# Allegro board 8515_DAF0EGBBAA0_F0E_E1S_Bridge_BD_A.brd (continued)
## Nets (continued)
IRQ_P12V_E1S_0_FLT_N: R171.1 U3.6 U22.C7 U35.N4
IRQ_P12V_E1S_1_FLT_N: R174.1 U4.6 U23.C7 U35.P4
IRQ_P12V_E1S_2_FLT_N: R179.1 U5.6 U24.C7 U35.P1
IRQ_P12V_E1S_3_FLT_N: R182.1 U6.6 U25.C7 U35.P5
IRQ_P12V_EDGE_FLT_N: R4589.2 U35.T11
IRQ_P12V_EDGE_FLT_N_R: R512.2 R4589.1 U33.C7 U34.9
IRQ_P12V_HSC_ALERT1_N: R707.2 U35.R3
IRQ_P12V_HSC_ALERT2_N: R708.2 U35.T2
IRQ_SMB_ALERT_N: GF1.OCP_A11 R185.2 R552.1
IRQ_SMB_ALERT_R_N: R552.2 U35.P9
IRQ_TMP75_ALERT_N: R291.1 U35.L4
JTAG_BIC_DEBUG_R_TDO: R674.2 U35.A11
JTAG_BIC_DEBUG_TCK: R4585.2 U35.D10
JTAG_BIC_DEBUG_TCK2: R4615.2 U35.A13
JTAG_BIC_DEBUG_TCK_R: J2.4 R4581.1 R4585.1
JTAG_BIC_DEBUG_TDI: R4586.2 U35.C10
JTAG_BIC_DEBUG_TDI2: R4616.2 U35.D11
JTAG_BIC_DEBUG_TDI_R: J2.8 R4582.1 R4586.1
JTAG_BIC_DEBUG_TDO: J2.6 R674.1 R4583.1
JTAG_BIC_DEBUG_TDO2: R4617.2 U35.C11
JTAG_BIC_DEBUG_TMS: R4584.2 U35.B11
JTAG_BIC_DEBUG_TMS2: R4618.2 U35.B12
JTAG_BIC_DEBUG_TMS_R: J2.2 R4580.1 R4584.1
JTAG_BIC_NTRST1: R596.2 R675.2 U35.A12
JTAG_BIC_NTRST2: R4613.2 R4614.2 U35.B13
JTAG_BIC_SRST_N: J2.10 R4587.1
LED_BIC_E1S_0: J4.A10 R216.1 R551.2
LED_BIC_E1S_1: J5.A10 R231.1 R553.2
LED_BIC_E1S_2: J6.A10 R246.1 R554.2
LED_BIC_E1S_3: J7.A10 R261.1 R725.2
LED_BIC_E1S_R_0: R551.1 U35.R11
LED_BIC_E1S_R_1: R553.1 U35.T12
LED_BIC_E1S_R_2: R554.1 U35.R12
LED_BIC_E1S_R_3: R725.1 U35.T13
LED_P12V_AUX: D10.1 R296.2
LED_P12V_E1S_ALL_GOOD: D11.C(\C\) U17.D
LED_P12V_E1S_ALL_GOOD_R: D11.A R297.2
LED_PWRGD_P12V_E1S_ALL: R298.1 R4670.1 U35.N5
LED_PWRGD_P12V_E1S_ALL_R: C304.1 R4670.2 U17.G
OSC1_OE: OSC1.1 R319.1
OSC1_VDD: C236.1 L6.2 OSC1.4(\VDD\) R661.1
OSC1_VDD_R: C237.1 R661.2
P3E_E1S_0_RX_DN0: GF1.A17 J4.A17
P3E_E1S_0_RX_DN1: GF1.A20 J4.A20
P3E_E1S_0_RX_DN2: GF1.A23 J4.A23
P3E_E1S_0_RX_DN3: GF1.A26 J4.A26
P3E_E1S_0_RX_DP0: GF1.A18 J4.A18
P3E_E1S_0_RX_DP1: GF1.A21 J4.A21
P3E_E1S_0_RX_DP2: GF1.A24 J4.A24
P3E_E1S_0_RX_DP3: GF1.A27 J4.A27
P3E_E1S_0_TX_DN0: GF1.B17 J4.B17
P3E_E1S_0_TX_DN1: GF1.B20 J4.B20
P3E_E1S_0_TX_DN2: GF1.B23 J4.B23
P3E_E1S_0_TX_DN3: GF1.B26 J4.B26
P3E_E1S_0_TX_DP0: GF1.B18 J4.B18
P3E_E1S_0_TX_DP1: GF1.B21 J4.B21
P3E_E1S_0_TX_DP2: GF1.B24 J4.B24
P3E_E1S_0_TX_DP3: GF1.B27 J4.B27
P3E_E1S_1_RX_DN0: GF1.A30 J5.A17
P3E_E1S_1_RX_DN1: GF1.A33 J5.A20
P3E_E1S_1_RX_DN2: GF1.A36 J5.A23
P3E_E1S_1_RX_DN3: GF1.A39 J5.A26
P3E_E1S_1_RX_DP0: GF1.A31 J5.A18
P3E_E1S_1_RX_DP1: GF1.A34 J5.A21
P3E_E1S_1_RX_DP2: GF1.A37 J5.A24
P3E_E1S_1_RX_DP3: GF1.A40 J5.A27
P3E_E1S_1_TX_DN0: GF1.B30 J5.B17
P3E_E1S_1_TX_DN1: GF1.B33 J5.B20
P3E_E1S_1_TX_DN2: GF1.B36 J5.B23
P3E_E1S_1_TX_DN3: GF1.B39 J5.B26
P3E_E1S_1_TX_DP0: GF1.B31 J5.B18
P3E_E1S_1_TX_DP1: GF1.B34 J5.B21
P3E_E1S_1_TX_DP2: GF1.B37 J5.B24
P3E_E1S_1_TX_DP3: GF1.B40 J5.B27
P3E_E1S_2_RX_DN0: GF1.A44 J6.A17
P3E_E1S_2_RX_DN1: GF1.A47 J6.A20
P3E_E1S_2_RX_DN2: GF1.A50 J6.A23
P3E_E1S_2_RX_DN3: GF1.A53 J6.A26
P3E_E1S_2_RX_DP0: GF1.A45 J6.A18
P3E_E1S_2_RX_DP1: GF1.A48 J6.A21
P3E_E1S_2_RX_DP2: GF1.A51 J6.A24
P3E_E1S_2_RX_DP3: GF1.A54 J6.A27
P3E_E1S_2_TX_DN0: GF1.B44 J6.B17
P3E_E1S_2_TX_DN1: GF1.B47 J6.B20
P3E_E1S_2_TX_DN2: GF1.B50 J6.B23
P3E_E1S_2_TX_DN3: GF1.B53 J6.B26
P3E_E1S_2_TX_DP0: GF1.B45 J6.B18
P3E_E1S_2_TX_DP1: GF1.B48 J6.B21
P3E_E1S_2_TX_DP2: GF1.B51 J6.B24
P3E_E1S_2_TX_DP3: GF1.B54 J6.B27
P3E_E1S_3_RX_DN0: GF1.A56 J7.A17
P3E_E1S_3_RX_DN1: GF1.A59 J7.A20
P3E_E1S_3_RX_DN2: GF1.A62 J7.A23
P3E_E1S_3_RX_DN3: GF1.A65 J7.A26
P3E_E1S_3_RX_DP0: GF1.A57 J7.A18
P3E_E1S_3_RX_DP1: GF1.A60 J7.A21
P3E_E1S_3_RX_DP2: GF1.A63 J7.A24
P3E_E1S_3_RX_DP3: GF1.A66 J7.A27
P3E_E1S_3_TX_DN0: GF1.B56 J7.B17
P3E_E1S_3_TX_DN1: GF1.B59 J7.B20
P3E_E1S_3_TX_DN2: GF1.B62 J7.B23
P3E_E1S_3_TX_DN3: GF1.B65 J7.B26
P3E_E1S_3_TX_DP0: GF1.B57 J7.B18
P3E_E1S_3_TX_DP1: GF1.B60 J7.B21
P3E_E1S_3_TX_DP2: GF1.B63 J7.B24
P3E_E1S_3_TX_DP3: GF1.B66 J7.B27
PD_BIC_ADCREXT0: R562.1 U35.F1
PD_BIC_ADCREXT1: R564.1 U35.G2
PD_BIC_ENTEST: R578.2 U35.A3
PD_FRU_E0: R275.2 R281.1 U15.1
PECI_R: R577.1 U35.H14
PRSNTA1_N: GF1.A10 R16.2 R18.1 R19.2 R20.1
PRSNTB0_N: GF1.B42 R18.2
PRSNTB1_N: GF1.A42 R19.1
PRSNTB2_N: GF1.A12 R16.1
PRSNTB3_N: GF1.B70 R20.2
PU_CLKREQ_0_N: J4.A11 R215.1
PU_CLKREQ_1_N: J5.A11 R230.1
PU_CLKREQ_2_N: J6.A11 R245.1
PU_CLKREQ_3_N: J7.A11 R260.1
PU_DB800_HI_BW: R480.2 R481.1 R723.1 U32.1(\^VHIBW_BYPM_LOBW#\)
PU_DB800_HI_BW_R: R723.2 U35.T3
PU_SMB_BMC_CPLD_SCL_G2: Q1.5 R427.1
PU_SMB_BMC_CPLD_SDA_G1: Q1.2 R426.1
PU_SMB_IPMB_AUX_SCL_G2: Q2.5 R429.1
PU_SMB_IPMB_AUX_SDA_G1: Q2.2 R428.1
PWRGD_EXP_PWROK: GF1.OCP_B1 R548.1
PWRGD_EXP_PWROK_R: R548.2 U35.L1
PWRGD_P1V2_STBY_R: C252.1 R90.2 R794.2 U36.5
PWRGD_P12V_AUX: R514.2 U35.T1
RESET_R_EXTRST_N: R4596.2 U43.1
RESET_R_N: R4595.1 R4596.1 R4612.2 U46.4
RESET_R_SRST_N: R4595.2 U42.2
RST_BIC_E1S_0_N: J4.B10 R539.2
RST_BIC_E1S_0_R_N: R539.1 R567.2 U35.P8
RST_BIC_E1S_1_N: J5.B10 R540.2
RST_BIC_E1S_1_R_N: R540.1 R569.2 U35.T5
RST_BIC_E1S_2_N: J6.B10 R541.2
RST_BIC_E1S_2_R_N: R541.1 R570.2 U35.R6
RST_BIC_E1S_3_N: J7.B10 R698.2
RST_BIC_E1S_3_R_N: R698.1 R699.2 U35.T6
RST_BIC_EXTRST_N: GF1.OCP_B4 R5.2 R4603.2
RST_BIC_SRST_N: GF1.OCP_B3 R792.2 R4602.2
RST_MB_N: R14.1 U35.M3
RST_MB_R_N: GF1.B10 R14.2
RST_SMB_E1S_0_N: J4.A9(\SMBRST#\) R550.1
RST_SMB_E1S_0_R_N: R550.2 R574.2 U35.M5
RST_SMB_E1S_1_N: J5.A9(\SMBRST#\) R695.1
RST_SMB_E1S_1_R_N: R575.2 R695.2 U35.R4
RST_SMB_E1S_2_N: J6.A9(\SMBRST#\) R561.1
RST_SMB_E1S_2_R_N: R561.2 R576.2 U35.N2
RST_SMB_E1S_3_N: J7.A9(\SMBRST#\) R563.1
RST_SMB_E1S_3_R_N: R563.2 R696.2 U35.N1
SELECT_RST_N: R4608.2 R4612.1 U46.1
SELECT_RST_R_N: R4608.1 U45.4(\Y\)
SGPIO_BMC_CLK_R: R783.1 R787.2 U35.B14
SGPIO_BMC_DOUT_R: R774.1 R778.1 U35.D12
SLOT_ID0_R: GF1.OCP_B7 R8.2
SLOT_ID1_R: GF1.OCP_A6 R6.1
SMB_BIC_E1S_0_R_SCL: R211.2 R598.2 U35.T16
SMB_BIC_E1S_0_R_SDA: R599.2 R665.2 U35.R16
SMB_BIC_E1S_1_R_SCL: R600.2 R666.2 U35.P15
SMB_BIC_E1S_1_R_SDA: R602.2 R667.2 U35.P16
SMB_BIC_E1S_2_R_SCL: R604.2 R709.2 U35.M13
SMB_BIC_E1S_2_R_SDA: R607.2 R710.2 U35.N15
SMB_BIC_E1S_3_R_SCL: R711.2 R713.2 U35.N16
SMB_BIC_E1S_3_R_SDA: R712.2 R714.2 U35.M14
SMB_BIC_SENSOR_R_SCL: R584.2 R611.2 U35.P13
SMB_BIC_SENSOR_R_SDA: R586.2 R613.2 U35.N14
SMB_BMC_CPLD_SCL: Q1.3 R12.2
SMB_BMC_CPLD_SCL_R: GF1.A7 R12.1 R21.2
SMB_BMC_CPLD_SDA: Q1.6 R13.2
SMB_BMC_CPLD_SDA_R: GF1.A8 R13.1 R22.2
SMB_CLKBUF_SCL_R: R494.2 U32.9
SMB_CLKBUF_SDA_R: R493.2 U32.10
SMB_E1S_0_R_SCL: J4.A7 R418.1
SMB_E1S_0_R_SDA: J4.A8 R419.1
SMB_E1S_0_SCL: R211.1 R224.1 R418.2
SMB_E1S_0_SDA: R225.1 R419.2 R665.1
SMB_E1S_1_R_SCL: J5.A7 R420.1
SMB_E1S_1_R_SDA: J5.A8 R421.1
SMB_E1S_1_SCL: R239.1 R420.2 R666.1
SMB_E1S_1_SDA: R240.1 R421.2 R667.1
SMB_E1S_2_R_SCL: J6.A7 R422.1
SMB_E1S_2_R_SDA: J6.A8 R423.1
SMB_E1S_2_SCL: R254.1 R422.2 R709.1
SMB_E1S_2_SDA: R255.1 R423.2 R710.1
SMB_E1S_3_R_SCL: J7.A7 R424.1
SMB_E1S_3_R_SDA: J7.A8 R425.1
SMB_E1S_3_SCL: R269.1 R424.2 R711.1
SMB_E1S_3_SDA: R270.1 R425.2 R712.1
SMB_FRU_SCL_R: R277.2 U15.6
SMB_FRU_SDA_R: R278.2 U15.5
SMB_INA230_E1S_0_SCL: R224.2 U11.5
SMB_INA230_E1S_0_SDA: R225.2 U11.4
SMB_INA230_E1S_1_SCL: R239.2 U12.5
SMB_INA230_E1S_1_SDA: R240.2 U12.4
SMB_INA230_E1S_2_SCL: R254.2 U13.5
SMB_INA230_E1S_2_SDA: R255.2 U13.4
SMB_INA230_E1S_3_SCL: R269.2 U14.5
SMB_INA230_E1S_3_SDA: R270.2 U14.4
SMB_IO_EXP_SCL: R796.1 U44.8 U48.22
SMB_IO_EXP_SDA: R795.1 U44.9 U48.23
SMB_IPMB_3V3AUX_SCL: R433.1 R680.2
SMB_IPMB_3V3AUX_SDA: R402.1 R681.2
SMB_IPMB_3V3SB_SCL: Q2.3 R1.1
SMB_IPMB_3V3SB_SCL_R: GF1.OCP_B11 R1.2 R23.2
SMB_IPMB_3V3SB_SDA: Q2.6 R9.1
SMB_IPMB_3V3SB_SDA_R: GF1.OCP_B12 R9.2 R24.2
SMB_IPMB_AUX_SCL_R: Q2.4(\S2\) R413.2 R433.2
SMB_IPMB_AUX_SDA_R: Q2.1 R402.2 R412.1
SMB_MB_CPLD_BIC_SCL: R209.2 R605.2 U35.R15
SMB_MB_CPLD_BIC_SDA: R210.2 R608.2 U35.P12
SMB_MB_CPLD_SCL: R209.1 R401.1
SMB_MB_CPLD_SCL_R: Q1.4(\S2\) R401.2 R411.1 R796.2
SMB_MB_CPLD_SDA: R210.1 R400.1
SMB_MB_CPLD_SDA_R: Q1.1 R400.2 R410.1 R795.2
SMB_MBBIC_BIC_R_SCL: R680.1 U35.L16
SMB_MBBIC_BIC_R_SDA: R681.1 U35.K16
SMB_SENSOR_SCL: R277.1 R290.1 R494.1 R584.1
SMB_SENSOR_SDA: R278.1 R289.1 R493.1 R586.1
SMB_TMP75_SCL_R: R290.2 U16.2
SMB_TMP75_SDA_R: R289.2 U16.1
SPI_BIC_CS0_R_N: R635.2 U35.A7
SPI_BIC_R_CLK: R785.2 R789.1 U35.A5
SPI_BIC_R_IO1: R782.1 R786.1 U35.B5
TDR_DIFF_85_BOT_DN: X3.4(\S2\) X4.1
TDR_DIFF_85_BOT_DP: X3.1 X4.4(\S2\)
TDR_DIFF_85_IN1_DN: X5.1 X6.4(\S2\)
TDR_DIFF_85_IN1_DP: X5.4(\S2\) X6.1
TDR_DIFF_85_IN2_DN: X7.4(\S2\) X8.1
TDR_DIFF_85_IN2_DP: X7.1 X8.4(\S2\)
TDR_DIFF_85_TOP_DN: X1.4(\S2\) X2.1
TDR_DIFF_85_TOP_DP: X1.1 X2.4(\S2\)
TDR_SE_50_OHM_BOT: J15.2 J15.3(\IO2\)
TDR_SE_50_OHM_IN1: J12.2 J12.3(\IO2\)
TDR_SE_50_OHM_IN2: J16.2 J16.3(\IO2\)
TDR_SE_50_OHM_TOP: J27.2 J27.3(\IO2\)
TMP75_AD0: R288.2 R294.1 U16.7
TMP75_AD1: R287.2 R293.1 U16.6
TMP75_AD2: R286.2 R292.1 U16.5
TMP75_ALERT_N_R: R291.2 R295.1 U16.3
TP_CLK_100M_E1S_0_DN: J4.A14
TP_CLK_100M_E1S_0_DP: J4.A15
TP_CLK_100M_E1S_1_DN: J5.A14
TP_CLK_100M_E1S_1_DP: J5.A15
TP_CLK_100M_E1S_2_DN: J6.A14
TP_CLK_100M_E1S_2_DP: J6.A15
TP_CLK_100M_E1S_3_DN: J7.A14
TP_CLK_100M_E1S_3_DP: J7.A15
TP_E1S_0_MFG: J4.B7
TP_E1S_0_RFU: J4.B8
TP_E1S_1_MFG: J5.B7
TP_E1S_1_RFU: J5.B8
TP_E1S_2_MFG: J6.B7
TP_E1S_2_RFU: J6.B8
TP_E1S_3_MFG: J7.B7
TP_E1S_3_RFU: J7.B8
TP_P3V3_E1S_0_PG: U26.D7
TP_P3V3_E1S_1_PG: U27.D7
TP_P3V3_E1S_2_PG: U28.D7
TP_P3V3_E1S_3_PG: U29.D7
TP_P3V3_EDGE_PG: U30.D7
TP_P12V_E1S_0_PG: U22.D7
TP_P12V_E1S_1_PG: U23.D7
TP_P12V_E1S_2_PG: U24.D7
TP_P12V_E1S_3_PG: U25.D7
UART_BIC5_R_RXD: J1.3 J30.1 R691.1 U35.A14
UART_BIC5_R_TXD: J1.1 R590.1 R679.2
UART_BIC_TXD: R679.1 R776.1 R780.2 U35.D13
UART_HOST_RXD: R591.2 U35.F12
UART_HOST_TXD: R690.2 U35.E12
UART_MB_RX: GF1.A14 R590.2 R591.1
UART_MB_TX: J30.2 R17.2 R690.1 R691.2
UART_MB_TX_R: GF1.A15 R17.1
USB2_FT232_BIC_DN: GF1.A68 R560.1
USB2_FT232_BIC_DP: GF1.A69 R559.1
USB_DN: R560.2 U35.F4
USB_DP: R559.2 U35.E4

Pads without a net: GF1 A9 A11 A70 B7 B8 B9 B68 B69 OCP_A1 OCP_A2 OCP_A3 OCP_A4 OCP_A5 OCP_A7 OCP_A8 OCP_A9 OCP_A14 OCP_B6 OCP_B8 OCP_B9 OCP_B14; GF2 A7 A8 A9 A10 A11 A12 A14 A15 A17 A18 A20 A21 A23 A24 A26 A27 A30 A31 A33 A34 A36 A37 A39 A40 A42 A44 A45 A47 A48 A50 A51 A53 A54 A56 A57 A59 A60 A62 A63 A65 A66 A68 A69 A70 B7 B8 B9 B10 B12 B14 B15 B17 B18 B20 B21 B23 B24 B26 B27 B30 B31 B33 B34 B36 B37 B39 B40 B42 B44 B45 B47 B48 B50 B51 B53 B54 B56 B57 B59 B60 B62 B63 B65 B66 B68 B69 B70; J2 7 9; NOREF#20 1; NOREF#27 1; NOREF#183 1; NOREF#226 1; NOREF#227 1; NOREF#228 1; U11 6 7 8 14 15 16; U12 6 7 8 14 15 16; U13 6 7 8 14 15 16; U14 6 7 8 14 15 16; U32 2 3 7 16 20 26 30; U35 A4 A6 A15 A16 B4 C4 C5 C12 C13 C14 E11 G15 G16 H1 H15 H16 J2 J4 J13 J14 J15 J16 K14 K15 L14 L15 M2 M12 M15 M16 N11 N12 P14 R10 T9; U45 1; U47 1

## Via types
v1: diameter 0.66, hole 0.33, TOP to BOTTOM, 138 vias
v2: diameter 0.762, hole 0.381, TOP to BOTTOM, 90 vias
v3: diameter 0.508, hole 0.254, TOP to BOTTOM, 1536 vias
v4: diameter 0.406, hole 0.203, TOP to BOTTOM, 279 vias
v5: diameter 0.762, hole 0.254, TOP to BOTTOM, 9 vias
v6: diameter 0.457, hole 0.254, TOP to BOTTOM, 8 vias

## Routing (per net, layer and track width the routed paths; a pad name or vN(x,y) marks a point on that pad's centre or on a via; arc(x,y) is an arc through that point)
GND: length 613.9
  TOP w0.203: v3(7.8,28.66) U33.A7 U33.B7
  TOP w0.254: R444.2 v3(37.41,59.89) ; v3(42.56,40.71) 42.58,40.69 U27.A7 ; U12.10 42.9,48.54 43.55,47.89 C76.2 ; U35.J6 v4(125.02,37.7) ; U28.B2 U28.C2 U28.C1 66.09,19.99 66.09,19.63 v3(66.06,19.61) ; R441.2 13.49,56.17 v3(13.46,56.13) ; v3(63.01,57.38) 63.39,57.76 C105.1 ; v3(126.07,16.24) 126.07,16.41 126.43,16.78 U30.A7 ; v3(36.44,25.62) 36.44,25.94 36.7,26.19 U32.8 ; v3(139.73,56.81) 139.91,56.63 C299.2 ; U29.B7 92.46,29.75 v3(92.66,29.95) ; v3(15.13,46.73) 15.32,46.58 15.33,46.48 U7.8 ; U27.B7 43.08,41.11 v3(42.78,41.42) ; R475.2 132.91,14.78 v3(132.42,14.28) ; v3(121.25,28.7) 121.28,28.73 R570.1 ; C108.1 v3(88.5,57.4) ; R467.2 v3(88.51,60.44) ; R453.2 v3(88.6,55.12) ; U14.10 96.24,39.4 96.89,38.74 C82.2 ; R448.2 v3(62.94,58.78) ; U35.H6 v4(125.82,39.3) ; U48.2 137.47,26.96 v3(137.8,26.62) 137.56,26.62 137.24,26.31 U48.3 ; v3(91.96,30) U29.A7 ; R567.1 v3(124.33,28.7) ; R569.1 v3(120.27,28.7) ; U11.10 16.77,50.3 17.43,49.64 C73.2 ; C102.1 37.97,58.88 v3(37.49,58.4) ; R465.2 v3(37.49,61.42) ; C96.1 v3(12.65,59.89) ; U33.B2 U33.C2 U33.C1 11.37,29.66 11.72,30.01 v3(11.91,30.01) ; C250.2 v3(119.78,23.86) ; R466.2 63.39,59.79 v3(62.99,60.2) ; U35.G8 v4(126.62,39.3) ; 95.05,34.11 94.58,33.64 U9.8 ; U27.B2 U27.C2 U27.C1 43.58,36.38 v3(43.66,36.3) ; v3(14.86,37.85) 14.86,38.28 14.5,38.64 U26.C1 U26.C2 U26.B2 ; v3(93.28,25.57) 93.28,25.77 92.96,26.09 U29.C1 U29.C2 U29.B2 ; U35.G7 v4(126.62,40.1) ; U30.B7 v3(126.09,17.28) ; U26.B7 14,42.52 v3(14.2,42.72) ; R445.2 v3(37.59,56.08) ; R449.2 v3(63.12,54.97) ; U28.B7 65.46,23.6 v3(65.66,23.8) ; v3(13.5,42.77) U26.A7 ; R699.1 v3(122.3,28.7) ; R464.2 v3(12.65,61.93) ; U35.G6 v4(125.82,40.1) ; U13.10 68.88,31.27 69.23,30.92 C79.2 ; R438.2 v3(12.65,60.91) ; U35.F3 v4(122.62,40.1) ; v3(64.96,23.85) U28.A7 ; R452.2 v3(88.42,58.93)
  TOP w0.305: R696.1 v3(117.85,33.02) ; U35.F6 v4(125.82,40.1) ; C157.2 39.48,33.54 v3(39.37,33.66) ; v3(114.44,47.48) 114.93,46.99 C284.1 R749.2 ; C132.1 133.38,16.89 v3(133.58,16.69) ; C291.1 120.09,46.99 v3(120.47,47.37) ; R768.2 v3(120.52,48.01) ; v3(118.49,46.99) 117.95,46.99 C292.1 ; R619.1 v3(122.17,48.39) R578.1 ; v3(112.3,11.74) 112.11,11.93 C311.2 ; R769.2 v3(118.49,48.01) ; R786.2 v3(123.19,49.02) ; R576.1 117.89,32 v3(117.88,32.02)
  TOP w0.33: Q11.4 60.99,20.08 60.69,19.78 60.12,19.78 v3(60.03,19.69) 59.69,19.35 Q11.1
  TOP w0.356: U22.B2 U22.C2 U22.C1 ; C91.2 110.75,17.24 v3(111.1,16.89) ; U24.B2 U24.C2 U24.C1 ; U30.C1 U30.C2 U30.B2 ; U23.B2 U23.C2 U23.C1 ; v3(135.3,53.5) 134.87,53.07 R532.1 ; R284.1 137.92,53.34 v3(137.67,53.59) ; U47.3 109,14.04 108.71,14.33 v3(108.71,14.48) ; R777.1 v3(135.64,51.06) ; Q11.4 61.2,20.7 62.01,20.7 62.26,20.44 R4653.2 ; U25.C1 U25.C2 U25.B2 ; v3(143.82,25.66) U48.21 ; U45.3 v3(108.07,17.74)
  TOP w0.381: C308.2 v3(107.82,22.82) ; J5.A28 v3(59.31,28.3) ; v3(57.3,31.9) J5.A22 v3(59.44,31.9) ; U35.M11 v4(129.82,35.3) ; J5.B16 v3(52.52,35.49) ; C321.2 58.96,21.79 58.14,22.61 v3(58.14,22.96) ; U35.G11 v4(129.82,40.1) ; v3(98.76,3.81) 99.08,3.49 GF2.A28 ; C176.2 21.61,26.1 v3(21.95,25.77) ; J6.A4 83.05,42.7 82.67,43.08 v3(82.67,43.31) 82.69,43.3 J6.A3 ; C79.2 69.62,30.61 v3(69.97,30.61) ; U35.M8 v4(126.62,35.3) ; R474.2 133.3,19.55 v3(133.74,19.55) ; J4.B16 v3(27.18,35.49) ; C236.2 v3(122.17,51.05) ; v3(108.29,31.9) J7.A22 v3(110.44,31.9) ; U35.K10 v4(129.01,36.9) ; GF2.A16 v3(91.88,3.53) ; J5.A3 57.19,43.3 v3(57.17,43.31) 57.17,43.08 57.55,42.7 J5.A4 ; v3(40.02,51.08) R236.2 ; U35.J9 v4(128.22,37.7) ; v3(34.09,37.06) 33.85,37.29 J4.A13 ; J4.B19 v3(27.18,33.69) ; U35.C6 v4(125.82,42.5) U35.D7 ; v3(116.71,22.2) 116.71,22.63 C252.2 R663.2 ; v3(132.45,51.07) 132.5,51.02 132.5,50.48 R675.1 R787.1 ; U43.3 v3(120.53,10.91) ; GF2.A55 v3(123,3.53) ; U35.G9 v4(128.22,40.1) ; C306.2 118.41,15.25 118.41,15.29 v3(118.46,15.33) ; R758.2 v3(114.45,37.08) ; GF2.A13 v3(90.08,3.56) ; R754.2 C287.1 119.46,36.26 119.63,36.26 119.82,36.44 119.82,36.54 v3(119.89,36.54) ; C314.2 145.95,27.68 146.33,27.3 v3(146.33,27.05) ; J6.A6 83.11,41.49 v3(82.8,41.81) 83.09,42.1 J6.A5 ; GF1.A55 v3(59.97,3.53) ; C307.2 121.82,13.49 v3(122.33,12.98) ; U35.D6 v4(125.02,42.5) ; v3(116.82,38.71) 116.82,38.45 117.42,37.85 C296.1 ; GF1.A67 v3(67.17,3.53) ; GF1.A43 52.77,3.64 v3(52.58,3.84) ; C285.1 v3(118.49,50.04) ; GF1.A13 v3(27.05,3.53) ; U35.C7 v4(125.82,43.3) U35.B7 ; v3(115.04,39.38) 115.05,39.4 C290.1 115.73,39.45 R760.2 ; J2.5 138.55,57.78 v3(138.66,57.89) ; v3(59.3,30.09) J5.A25 v3(57.28,30.09) ; GF2.A41 v3(110.29,3.53) ; GF1.A49 v3(56.37,3.53) ; GF2.A67 v3(130.2,3.53) ; J4.B13 v3(27.13,37.29) ; J6.B13 v3(78.11,37.3) ; GF2.A29 103.09,3.77 v3(103.17,3.86) ; R195.2 v3(10.45,44.7) ; v3(31.8,31.89) J4.A22 v3(33.94,31.89) ; Q9.1 7.89,37.25 v3(7.4,37.74) ; U35.M7 v4(125.82,35.3) ; R285.1 v3(137.16,40.64) ; v3(39.8,3.91) 40.06,3.65 GF1.A29 ; v3(59.31,37.36) 59.24,37.3 J5.A13 ; GF1.OCP_A10 v3(13.06,3.53) ; v3(9.13,35.95) Q9.4 10.92,35.95 11.21,35.66 C319.2 ; J6.A2 82.92,43.9 v3(82.72,44.09) 83.12,44.49 J6.A1 ; v3(117.22,41.02) 117.22,41.8 C204.2 ; v3(136.45,44.4) 136.54,44.3 R505.1 ; U35.J10 v4(129.01,37.7) ; v3(33.81,30.09) J4.A25 v3(31.78,30.09) ; v3(37.34,38.23) C116.1 37.95,38.23 C165.1 ; v3(31.71,35.49) J4.A16 ; v3(16.02,57.76) 16.07,57.71 U22.C1 ; v3(108.28,30.09) J7.A25 v3(110.3,30.09) ; GF1.A52 v3(58.17,3.53) ; U48.12 137.66,20.46 v3(137.72,20.4) ; U35.L10 v4(129.01,36.1) ; v3(110.31,28.3) J7.A28 ; J5.B28 v3(52.58,28.3) ; v3(84.81,28.3) J6.A28 ; U35.K9 v4(128.22,36.9) ; v3(82.78,33.7) J6.A19 v3(84.9,33.7) ; U35.G10 v4(129.01,40.1) ; J7.B16 v3(103.57,35.49) ; C78.2 69.22,29.24 68.38,29.24 67.92,29.69 v3(67.92,29.97) ; J6.B28 v3(78.13,28.3) ; v3(91.78,57.05) 91.84,57 U25.C1 ; J5.B22 v3(52.47,31.9) ; R192.2 46.18,43.32 v3(46.18,43.91) ; GF2.A43 v3(115.8,3.86) ; J4.B25 v3(27.18,30.09) ; GF1.A58 v3(61.77,3.53) ; U35.H9 v4(128.22,39.3) ; J7.B25 v3(103.64,30.09) ; v3(82.71,35.49) J6.A16 ; U35.A1 v4(121.02,44.9) ; GF1.A46 v3(54.57,3.53) ; U35.K7 v4(125.82,36.9) ; GF2.A46 v3(117.6,3.53) ; GF1.A38 v3(45.46,3.53) ; v3(108.21,35.49) J7.A16 ; v3(9.88,43.69) C62.2 10.49,43.68 C164.1 ; R575.1 118.24,27.13 117.82,26.71 v3(117.73,26.71) ; v3(74.42,43.13) 74.42,40.26 75.31,39.37 R244.1 ; R475.2 R463.2 C132.1 ; v3(81.92,37.97) 81.92,37.72 82.34,37.3 J6.A13 ; U35.L7 v4(125.82,36.1) ; v3(118.41,50.7) 118.06,51.05 R750.2 ; U35.K11 v4(129.82,36.9) ; v3(84.94,31.9) J6.A22 v3(82.8,31.9) ; GF2.A49 v3(119.4,3.53) ; C92.2 116.07,16.16 v3(116.18,16.28) ; U35.L8 v4(126.62,36.1) ; GF1.A61 v3(63.57,3.53) ; C168.1 v3(130.89,13.19) ; GF2.A38 v3(108.49,3.53) ; U35.H8 v4(126.62,39.3) ; C75.2 43.66,45.49 v3(43.61,45.44) ; R730.1 v3(127.38,28.7) ; J7.B22 v3(103.63,31.9) ; C69.2 61.85,25.7 v3(61.85,25.07) ; v3(119.63,15.81) 119.44,15.62 R308.2 ; U35.M10 v4(129.01,35.3) ; U35.L9 v4(128.22,36.1) ; v3(57.28,33.7) J5.A19 v3(59.4,33.7) ; GF2.A58 v3(124.8,3.53) ; GF2.A32 v3(104.89,3.53) ; J4.B22 v3(27.18,31.89) ; U35.M9 v4(128.22,35.3) ; J5.B13 v3(52.54,37.3) ; U35.J7 v4(125.82,37.7) ; v3(82.78,30.09) J6.A25 v3(84.81,30.09) ; J6.B16 v3(78.11,35.49) ; U35.K6 v4(125.02,36.9) ; C125.1 v3(130.86,14.21) ; GF1.A35 v3(43.66,3.53) ; J4.A2 32.13,43.89 31.75,44.28 v3(31.75,44.3) 31.95,44.49 J4.A1 ; v3(66.31,56.9) 66.36,56.85 U24.C1 ; J7.B28 v3(103.66,28.3) ; J7.B19 v3(103.59,33.7) ; C310.1 108.44,17.17 v3(107.94,16.67) ; J5.A1 57.62,44.49 v3(57.22,44.09) 57.42,43.9 J5.A2 ; R564.2 R562.2 ; v3(78.11,33.7) J6.B19 ; R785.1 v3(124.21,49.02) ; v3(130.29,17.69) 130.25,17.72 129.75,17.72 U30.C1 ; v3(36.02,3.53) 36.05,3.49 GF1.A28 ; v3(114.43,36.45) 114.66,36.45 C289.1 ; v3(110.4,33.7) J7.A19 v3(108.28,33.7) ; v3(74.49,54.2) 74.54,54.25 R177.1 ; J4.A5 32.09,42.09 v3(31.8,41.81) 32.11,41.49 J4.A6 ; U35.K8 v4(126.62,36.9) ; R527.1 v3(137.35,50.44) ; GF1.A41 v3(47.26,3.53) ; J4.B28 v3(29.31,28.29) ; U42.3 v3(115.9,12.13) ; J5.B25 v3(52.58,30.09) ; GF1.OCP_A13 14.86,3.5 v3(14.88,3.53) ; R189.2 17.78,45.47 v3(18.03,45.21) ; GF1.A25 v3(34.25,3.53) ; J6.B22 v3(78.12,31.9) ; C85.2 91.69,46.97 v3(91.69,48.13) ; U35.H7 v4(125.82,39.3) ; v3(127.64,61.04) 127.18,61.49 U15.4 ; GF1.A22 v3(32.45,3.53) ; R651.2 v3(144.96,55.02) ; U35.J8 v4(126.62,37.7) ; v3(31.78,33.69) J4.A19 v3(33.9,33.69) ; GF2.A22 v3(95.48,3.53) ; U35.N13 v4(131.42,34.5) ; U35.H10 v4(129.01,39.3) ; v3(33.81,28.29) J4.A28 ; U16.4 v3(94.92,50.54) ; J5.B19 v3(52.49,33.7) ; U23.C1 v3(40.79,57.2) ; J7.B13 v3(103.67,37.3) ; 136.97,56.52 v3(138.68,56.52) ; J5.A16 v3(57.21,35.49) ; GF2.A61 v3(126.6,3.53) ; U35.E6 v4(125.02,41.7) ; GF1.A32 v3(41.86,3.53) ; v3(86.87,48.21) 86.87,46.97 87.25,46.59 R294.2 ; U35.L11 v4(129.82,36.1) ; GF2.A35 v3(106.69,3.53) ; GF1.A64 v3(65.37,3.53) ; GF2.A25 v3(97.28,3.53) ; GF2.A19 v3(93.68,3.53) ; GF2.A64 v3(128.4,3.53) ; GF2.A52 v3(121.2,3.53) ; v3(118.62,57.91) 118.62,57.92 ; U35.H11 v4(129.82,39.3) ; GF1.A19 v3(30.65,3.53) ; J5.A5 57.59,42.1 v3(57.21,41.72) 57.39,41.72 57.61,41.49 J5.A6 ; U35.L6 v4(125.02,36.1) ; R784.1 v3(125.22,51.05) ; U35.J11 v4(129.82,37.7) ; J6.B25 v3(78.11,30.09) ; GF1.A16 v3(28.85,3.56) ; J7.A13 v3(108.25,37.3)
  TOP w0.457: D10.2 146.21,21.85 v3(146.33,21.97) ; R4643.2 v3(5.95,38.3)
  TOP w0.508: v3(7.29,26.8) C171.2 ; R229.1 49.88,38.56 v3(49.35,38.56) ; R455.2 9.67,39.46 v3(9.18,39.95) 10.36,39.95 C113.1 10.65,39.64 R490.2 ; C82.2 97.17,38.74 v3(97.57,38.34) ; C150.2 41.55,23.17 42.06,23.68 v3(42.06,24.32) ; R306.2 118.9,18.52 v3(119.05,18.38) ; v3(12.06,54.74) 12.06,54.38 R223.2 ; v3(63.48,28.24) 63.25,28.01 62.92,28.01 C67.2 ; v3(44.32,47.89) C76.2 ; 118.62,57.92 118.62,58.28 R417.2 ; R461.2 C131.1 92.94,25.02 93.04,25.11 93.04,25.32 v3(93.28,25.57) ; C63.2 39.46,42.74 v3(39.19,43.01) ; Q3.S v3(1.59,28.38) ; v3(98.36,34.86) 98.17,35.05 98.17,35.18 98.15,35.2 R259.1 ; C50.2 22.91,63.04 ; v3(38.85,20.86) 38.43,20.86 37.55,21.74 37.55,22.65 C149.2 ; R253.2 63.77,32.62 63.53,32.87 v3(63.53,33.04) 63.38,33.04 62.97,33.45 R252.2 ; C169.2 7.29,25.83 v3(7.28,25.82) ; R204.2 60.7,27.98 v3(60.3,27.58) ; R522.1 21.58,28.72 v3(21.95,29.09) ; v3(122.45,13.82) 122.45,13.87 122.2,14.12 C86.1 ; C60.2 10.79,46.74 9.53,48.01 v5(9.53,48.26) ; R175.2 24.7,62.33 24.74,62.28 ; R266.2 v3(95.25,44.45) ; R214.1 v3(25.6,40.43) ; v3(43.94,32.13) 43.82,32.25 C147.2 C148.2 ; R221.2 v3(11.68,50.8) ; R492.2 v3(17.88,37.64) ; C68.2 v3(91.17,33.17) ; R562.2 v3(117.86,41.02) ; C72.2 v3(16.92,47.86) ; C66.2 v3(88.9,35.05) ; R197.2 95.37,34.44 95.05,34.11 ; R237.2 v3(38.09,48.64) ; R267.2 v3(90.42,43.94) ; v3(44.36,28.36) 44.19,28.19 C158.2 ; R477.2 R481.2 v3(35.69,33.42) ; v3(4.32,28.38) 4.32,27.6 Q4.S ; C58.2 98.68,63.09 ; v3(17.41,37.13) C128.1 ; C52.2 47.68,62.92 ; C84.1 118.34,57.63 v3(118.62,57.91) ; v3(96.39,36.68) 96.72,36.68 C81.2 ; v3(89.94,25.95) 89.39,25.39 R503.2 ; C73.2 17.67,49.64 18.92,48.39 v5(18.92,48.13) ; R183.2 74.22,63.07 ; C122.1 88.24,27.28 C167.1 87.63,28.94 87.63,31.05 87.36,31.31 ; R184.2 99.69,63.09 ; R176.2 48.69,62.99 ; C204.2 C202.2 ; C56.2 73.2,62.94
  BOTTOM w0.254: v3(45.03,58.46) 44.93,58.37 44.77,58.37 C110.2 ; v3(127.1,45.93) 127.1,45.8 126.99,45.7 126.99,45.29 C300.2 ; v4(129.82,35.3) 130.21,34.91 C298.2 ; v3(127.42,31.19) 127.42,32.5 C301.2 ; v3(139.79,20.63) 139.98,20.63 140.5,21.15 U44.5 ; C239.2 125.43,37.2 125.13,36.9 v4(125.02,36.9) ; R298.2 138.29,26.14 v3(137.8,26.62) ; C313.2 v4(125.02,36.1) ; R499.2 68.91,20.22 v3(68.91,19.71) ; C240.2 123.03,37.4 123.33,37.7 v4(123.42,37.7) ; U35.F3 122.9,40.5 122.62,40.21 122.62,40.19
  BOTTOM w0.279: v4(126.62,43.3) 126.62,43.19 126.9,42.91 C232.2
  BOTTOM w0.305: C228.2 122.31,40.5 122.62,40.19 v4(122.62,40.1) ; v3(118.49,46.99) 117.95,46.99 C292.1 ; v3(119.89,36.54) 119.92,36.51 C312.2 ; R769.2 v3(118.49,48.01) ; R569.1 v3(120.27,28.7) ; R768.2 v3(120.52,48.01) ; v3(120.47,47.37) 120.09,46.99 C291.1 ; v4(120.12,40.9) C230.2 120.61,40.59 121.33,40.59 C229.2 ; C297.2 v4(133.01,37.7)
  BOTTOM w0.356: v3(133.51,51.04) 133.6,50.95 R4614.1 ; v3(132.45,51.07) 132.42,51.05 132.42,50.55 R778.2 ; Q6.4 45.56,51.13 44.87,51.82 44.48,51.82 44.26,52.03 Q6.1
  BOTTOM w0.381: GF1.A2 20.45,3.68 ; 20.45,3.68 20.23,3.68 19.85,3.3 GF1.A1 ; 20.45,3.68 20.45,3.68 ; v3(22.48,7.11) v3(22.48,6.22) v3(22.48,5.33) v3(22.48,4.45) 22.48,4.09 22.25,3.86 22.25,3.86 GF1.A5 ; R457.2 41.8,34.7 41.36,35.15 R496.2 41.36,35.93 v3(41.35,35.94) ; GF1.A46 v3(54.57,3.53) ; C210.2 126.21,42.1 v4(125.82,42.5) ; GF2.A32 v3(104.89,3.53) ; GF2.A52 v3(121.2,3.53) ; R4658.2 85.86,26.06 84.28,26.06 v3(83.83,26.52) ; v3(91.69,48.13) 91.19,47.62 R293.2 ; C320.2 44.34,41.49 43.79,40.94 43.25,40.94 v3(42.78,41.42) ; GF1.A52 v3(58.17,3.53) ; v3(24.74,54.51) 24.74,54.84 24.36,55.22 R4622.2 ; v3(130.48,51.09) 130.56,51.01 R518.1 ; v3(61.85,24.31) 61.85,20.1 62.72,19.23 R500.2 ; v3(93.28,25.57) 93.28,25.74 93.69,26.15 93.69,26.83 93.42,27.1 C322.2 ; v3(84.08,6.98) v3(84.08,6.09) v3(84.08,5.21) v3(84.08,4.32) GF2.A3 ; R570.1 121.28,28.73 v3(121.25,28.7) ; v3(39.8,3.91) 40.06,3.65 GF1.A29 ; v3(43.61,45.44) 43.92,45.75 R4648.2 ; GF1.A43 52.77,3.64 v3(52.58,3.84) ; C315.2 18.41,52.81 v3(18.01,53.21) ; GF2.A25 v3(97.28,3.53) ; GF2.A41 v3(110.29,3.53) ; v3(115.9,12.13) 115.9,12.17 116.28,12.55 U46.3 ; C285.1 v3(118.49,50.04) ; v3(99.49,53.87) 98.95,53.33 R4634.2 ; R196.2 C61.2 43.76,44.62 43.97,44.83 v3(43.97,44.91) ; R279.2 127.25,61.74 127.64,61.36 v3(127.64,61.04) ; GF2.A6 85.88,3.66 ; R574.1 118.24,27.13 117.82,26.71 v3(117.73,26.71) ; v3(118.41,50.7) 118.31,50.7 118.29,50.72 118.19,50.72 117.88,51.03 R750.2 ; R459.2 65.45,20.42 C130.1 66.2,19.74 v3(66.06,19.61) ; C235.2 124.23,51.07 v3(124.21,51.05) ; R292.2 91.49,51.05 v3(91.69,51.26) 91.69,51.86 C318.2 ; GF2.A55 v3(123,3.53) ; GF1.A38 v3(45.46,3.53) ; GF1.A49 v3(56.37,3.53) ; R730.1 v3(127.38,28.7) ; Q12.4 88.28,28.35 88.78,27.84 89.36,27.84 89.58,27.63 Q12.1 89.58,26.31 v3(89.94,25.95) ; C246.2 v4(125.02,42.5) C247.2 ; v3(92.66,29.95) 92.66,29.48 C124.2 ; GF2.A4 84.68,3.52 ; v3(36.02,3.53) 36.05,3.49 GF1.A28 ; v3(42.56,40.71) 42.16,41.12 C118.2 ; v3(135.64,51.06) R777.1 ; C296.1 C207.2 116.98,38.86 v3(116.82,38.71) ; v3(49.73,53.95) 49.49,53.7 R172.1 47.35,53.7 46.89,53.24 R4626.2 ; GF2.A13 v3(90.08,3.56) ; v3(98.76,3.81) 99.08,3.49 GF2.A28 ; GF2.A5 85.28,3.61 85.6,3.94 v3(85.6,4.32) v3(85.6,5.21) v3(85.6,6.1) v3(85.6,6.99) ; GF1.A16 v3(28.85,3.56) ; v3(92.33,51.26) 92.97,51.9 Q8.4 94.85,51.9 95.12,52.17 95.12,53.11 95.22,53.2 Q8.1 ; v3(19.28,49.81) 20.57,49.81 21.88,51.12 Q5.4 21.88,52.44 21.44,52.88 20.75,52.88 20.58,53.05 Q5.1 ; C244.2 122.92,45.49 v4(123.19,45.21) 122.92,44.94 122.92,44.83 C243.2 ; GF1.A19 v3(30.65,3.53) ; v3(46.18,43.91) 47.46,43.91 48.04,43.32 Q10.1 ; C295.2 143.61,29.21 v3(143.46,29.36) ; GF1.A58 v3(61.77,3.53) ; R791.1 v3(126.36,30.71) ; GF1.A35 v3(43.66,3.53) ; v3(40.46,53.29) C316.2 ; GF2.A1 82.88,3.25 83.19,3.56 ; R617.1 120.73,45.18 v4(121.02,44.9) ; GF2.A58 v3(124.8,3.53) ; GF1.OCP_A10 v3(13.06,3.53) ; v3(20.08,59.1) 20.23,59.24 21.41,59.24 C109.2 ; v4(131.42,34.5) C218.2 ; GF1.A22 v3(32.45,3.53) ; R577.2 134.78,52.98 v3(135.3,53.5) ; GF1.A25 v3(34.25,3.53) ; GF2.A64 v3(128.4,3.53) ; R567.1 v3(124.33,28.7) ; C289.1 R758.2 v3(114.45,37.08) ; v3(14.88,3.53) 14.86,3.5 GF1.OCP_A13 ; R11.2 14.99,11.68 v3(15.14,11.53) ; v3(112.3,11.74) 112.3,13.57 C309.2 ; GF2.A43 v3(115.8,3.86) ; GF2.A29 103.09,3.77 v3(103.17,3.86) ; GF2.A49 v3(119.4,3.53) ; v3(1.59,28.38) 1.76,28.21 C303.2 ; R281.2 v3(127.65,57.93) ; GF1.A13 v3(27.05,3.53) ; Q7.4 70.85,58.99 70.47,58.61 v3(70.47,58.1) 70.56,58.19 72.25,58.19 72.63,57.81 Q7.1 ; GF1.A67 v3(67.17,3.53) ; C302.2 4.3,28.36 v3(4.32,28.38) ; GF1.A3 v3(21.05,4.42) v3(21.05,5.31) v3(21.05,6.19) v3(21.05,7.11) ; GF2.A22 v3(95.48,3.53) ; GF1.A41 v3(47.26,3.53) ; GF2.A2 83.48,3.52 ; GF2.A35 v3(106.69,3.53) ; GF1.A55 v3(59.97,3.53) ; GF2.A61 v3(126.6,3.53) ; GF1.A6 22.85,3.8 ; GF1.A32 v3(41.86,3.53) ; R780.1 145.39,36.93 v3(145.59,36.73) ; GF2.A38 v3(108.49,3.53) ; GF1.A4 21.65,3.62 ; R280.2 v3(127.65,58.91) ; GF2.A16 v3(91.88,3.53) ; Q6.4 45.56,49.48 v3(45.21,49.13) ; GF1.A64 v3(65.37,3.53) ; GF2.A67 v3(130.2,3.53) ; C215.2 C213.2 127.14,42.22 127.14,42.75 C232.2 ; GF2.A19 v3(93.68,3.53) ; GF1.A61 v3(63.57,3.53) ; GF2.A46 v3(117.6,3.53) ; C121.2 65.66,23.34 v3(65.66,23.8)
  BOTTOM w0.457: R169.1 24.44,58.44 v3(24.71,58.17) ; v3(66.6,60.55) 67.11,60.05 67.11,59.23 67.44,58.9 C317.2 ; v3(74.49,54.2) 74.12,54.2 73.55,54.77 R4630.2 ; v3(145.59,35.36) 144.66,35.36 C304.2 144.14,34.32 144.64,33.82 U17.S ; Q10.4 49.34,41.33 49.8,41.78 v3(50.52,41.78) ; C90.2 C89.2 133.12,17.14 v3(133.58,16.69)
  BOTTOM w0.508: R509.2 8.31,29.17 v3(7.8,28.66) ; C48.2 24.69,61.74 ; R510.2 11.57,30 11.9,30 v3(11.91,30.01) ; 49.73,61.21 49.73,61.21 C49.2 ; C55.2 100.68,61.26 ; C129.1 R457.2 ; C115.2 11.13,41.65 11.13,42.44 v3(9.88,43.69) ; C170.1 12.4,31.72 12.4,30.81 v3(12.29,30.7) ; v3(130.29,17.69) 130.05,17.45 C127.2 ; C111.2 70.2,57.43 v3(70.54,57.43) ; R203.2 93.6,34.16 v3(93.73,34.29) ; R511.2 12.39,28.03 v3(11.94,28.03) ; C180.2 v3(12.5,26.6) ; R497.2 43.59,36.37 v3(43.66,36.3) ; C54.2 75.14,61.23
  vias: v1(1.71,35.37) v1(3.92,35.81) v1(20.7,12.19) v1(22.52,24.49) v1(22.51,21.79) v1(22.53,18.93) v1(97.97,58.31) v1(120.55,55.56) v1(122.1,54.59) v2(127.28,12.12) v2(127.33,10.67) v3(0.76,53.54) v3(0.76,49.27) v3(0.76,41.49) v3(0.76,38.3) v3(0.76,33.22) v3(0.76,28.14) v3(0.76,23.06) v3(0.77,17.71) v3(0.77,10.56) v3(1.45,8.47) v3(1.88,55.12) v3(1.87,37.43) v3(1.87,36.79) v3(2.5,37.43) v3(2.5,36.79) v3(3.77,37.43) v3(3.77,36.79) v3(4.41,37.43) v3(4.41,36.79) v3(5.47,8.48) v3(6.96,55.12) v3(7.37,5.59) v3(10.08,20.25) v3(10.08,19.43) v3(10.15,15.21) v3(10.75,20.25) v3(10.75,19.43) v3(10.79,15.21) v3(11.38,20.25) v3(11.38,19.43) v3(11.45,15.21) v3(11.73,55.42) v3(12.02,20.25) v3(12.02,19.43) v3(12.09,15.21) v3(12.65,20.25) v3(12.65,19.43) v3(12.72,15.21) v3(13.23,63.13) v3(13.18,37.64) v3(14.14,51.08) v3(14.14,50.07) v3(14.07,37.64) v3(14.35,46.71) v3(14.61,54.76) v3(14.61,54.03) v3(14.83,62.36) v3(14.86,61.59) v3(15.24,51.05) v3(15.24,50.04) v3(15.77,5.69) v3(15.77,4.67) v3(17.68,7.77) v3(18.31,63.13) v3(18.85,37.62) v3(19.14,7.07) v3(19.18,30.65) v3(19.66,37.59) v3(19.81,30.44) v3(20.22,58.12) v3(20.55,58.66) v3(23.39,63.13) v3(24.71,59.18) v3(24.71,57.15) v3(27.94,49.66) v3(28.65,13.97) v3(30.03,31.54) v3(30.03,29) v3(30.54,35.86) v3(30.54,33.32) v3(31.19,13.97) v3(31.67,43.31) v3(32.77,21.97) v3(33.02,49.66) v3(35.31,21.97) v3(35.78,29.53) v3(36.39,4.62) v3(36.78,61.54) v3(36.78,56.46) v3(36.78,51.38) v3(37.8,54.89) v3(38.23,29.21) v3(38.23,28.32) v3(38.35,27.05) v3(38.42,7.86) v3(38.56,54.94) v3(38.6,22.21) v3(39.16,34.26) v3(39.5,29.21) v3(39.5,27.05) v3(39.83,63.12) v3(39.75,60.58) v3(39.76,5.48) v3(40.28,49.3) v3(40.28,48.29) v3(40.44,60.53) v3(40.69,29.21) v3(40.69,28.07) v3(40.69,27.05) v3(41.07,60.53) v3(41.14,22.21) v3(41.38,49.3) v3(41.38,48.29) v3(41.71,34.14) v3(41.99,35.92) v3(43,44.96) v3(43.81,33.08) v3(44.91,63.12) v3(44.93,57.58) v3(45.44,57.96) v3(46.33,33.02) v3(47.65,40.36) v3(48.54,40.34) v3(48.59,6.86) v3(49.61,63.09) v3(49.73,58.01) v3(49.73,57) v3(49.73,55.98) v3(49.73,54.71) v3(49.73,52.93) v3(50.75,7.75) v3(52.47,4.93) v3(53.67,49.66) v3(55.53,31.54) v3(55.53,29) v3(56.03,35.87) v3(56.03,33.33) v3(58.37,49.66) v3(62.2,50.93) v3(62.28,61.19) v3(62.28,55.96) v3(63.12,53.92) v3(63.8,53.92) v3(64.64,63.12) v3(65.2,60.55) v3(65.84,27.81) v3(65.85,60.55) v3(65.95,32.02) v3(65.95,31) v3(66.65,27.79) v3(67.03,32.03) v3(67.03,31.01) v3(69.3,5.18) v3(69.6,19.66) v3(69.72,63.12) v3(71.93,52.1) v3(71.93,51.38) v3(73.44,6.96) v3(74.8,63.12) v3(75.23,58.12) v3(75.23,57.1) v3(75.23,56.08) v3(75.23,53.04) v3(78.52,6.95) v3(79.38,49.66) v3(80.44,29.24) v3(81.03,31.54) v3(81.54,35.87) v3(81.54,33.33) v3(82.56,4.68) v3(83.87,49.66) v3(86.11,31.52) v3(86.13,30.81) v3(87.73,51) v3(87.78,61.21) v3(87.78,56.13) v3(88.67,54.08) v3(89.74,54.1) v3(90.25,62.31) v3(90.3,61.59) v3(90.42,63.12) v3(93.64,40.16) v3(93.64,39.15) v3(94.41,34.21) v3(94.72,40.16) v3(94.72,39.14) v3(95.94,58.27) v3(95.96,57.35) v3(96.09,27.41) v3(96.42,57.81) v3(96.82,27.41) v3(99.39,4.5) v3(99.69,7.06) v3(100.58,63.12) v3(100.74,58.24) v3(100.74,57.23) v3(100.74,56.21) v3(100.74,53.16) v3(102.74,6.43) v3(102.77,4.52) v3(104.27,49.66) v3(106.53,31.54) v3(106.53,29) v3(107.03,35.87) v3(107.03,33.33) v3(108.32,44.07) v3(108.32,43.43) v3(109.35,49.66) v3(111.2,4.3) v3(111.3,6.3) v3(112.7,50.93) v3(112.78,54.64) v3(113.33,7.76) v3(115.44,6.1) v3(115.48,4.59) v3(116.33,25.91) v3(116.33,25.15) v3(116.69,56.31) v3(116.79,61.34) v3(118.19,17.35) v3(119.63,17.4) v3(119.74,54.6) v3(119.91,63.12) v3(120.59,52.12) v3(122.94,21.69) v3(122.94,21.06) v3(122.86,11.71) v3(122.86,10.95) v3(123.98,22.61) v3(124.64,22.61) v3(124.84,53.59) v3(124.99,63.12) v3(125.43,11.86) v3(125.48,11.02) v3(126.42,11.53) v3(128.78,25.15) v3(130.07,63.12) v3(130.68,24.49) v3(130.67,23.82) v3(132.3,5.3) v3(132.3,3.88) v3(134.7,32.97) v3(135.04,8.5) v3(135.15,63.12) v3(135.64,49.03) v3(139.76,59.8) v3(140.23,63.12) v3(140.9,32.23) v3(144.96,63.12) v3(146.33,59.26) v3(146.33,54.23) v3(146.33,51.69) v3(146.33,47.88) v3(146.33,41.53) v3(146.33,36.94) v3(146.33,16.89) v3(146.3,8.64)
GND1: length 14.4
  TOP w0.508: J19.3 v3(-27.61,105.57) ; J18.3 v3(-9.52,28.79) ; J25.3 v3(-22.53,28.79) ; J20.3 v3(-27.61,28.79) ; J8.3 v3(-14.6,28.79) ; J26.3 v3(-22.53,105.57) ; J17.3 v3(-9.52,75.22) ; J9.3 v3(-14.6,75.22)
  BOTTOM w0.508: J24.3 v3(-25.07,105.57) ; J21.3 v3(-19.99,105.57) ; J13.3 v3(-12.06,28.79) ; J10.3 v3(-6.98,28.79) ; J23.3 v3(-25.07,28.79) ; J22.3 v3(-19.99,28.79) ; J11.3 v3(-6.98,75.22) ; J14.3 v3(-12.06,75.22)
  vias: v3(-28.88,101.99) v3(-28.88,32.38) v3(-28.25,105.29) v3(-28.25,104.07) v3(-28.25,30.29) v3(-28.25,29.07) v3(-26.96,105.29) v3(-26.96,104.07) v3(-26.96,30.29) v3(-26.96,29.07) v3(-26.34,101.99) v3(-26.34,32.38) v3(-25.71,105.29) v3(-25.71,104.07) v3(-25.71,30.29) v3(-25.71,29.07) v3(-24.42,105.29) v3(-24.42,104.07) v3(-24.42,30.29) v3(-24.42,29.07) v3(-23.8,101.99) v3(-23.8,32.38) v3(-23.17,105.29) v3(-23.17,104.07) v3(-23.17,30.29) v3(-23.17,29.07) v3(-21.88,105.29) v3(-21.88,104.07) v3(-21.88,30.29) v3(-21.88,29.07) v3(-21.26,101.99) v3(-21.26,32.38) v3(-20.63,105.29) v3(-20.63,104.07) v3(-20.63,30.29) v3(-20.63,29.07) v3(-19.34,105.29) v3(-19.34,104.07) v3(-19.34,30.29) v3(-19.34,29.07) v3(-18.93,101.96) v3(-18.91,32.39) v3(-15.87,71.64) v3(-15.87,32.38) v3(-15.25,74.94) v3(-15.25,73.72) v3(-15.25,30.29) v3(-15.25,29.07) v3(-13.95,74.94) v3(-13.95,73.72) v3(-13.95,30.29) v3(-13.95,29.07) v3(-13.33,71.64) v3(-13.33,32.38) v3(-12.71,74.94) v3(-12.71,73.72) v3(-12.71,30.29) v3(-12.71,29.07) v3(-11.41,74.94) v3(-11.41,73.72) v3(-11.41,30.29) v3(-11.41,29.07) v3(-10.79,71.64) v3(-10.79,32.38) v3(-10.17,74.94) v3(-10.17,73.72) v3(-10.17,30.29) v3(-10.17,29.07) v3(-8.87,74.94) v3(-8.87,73.72) v3(-8.87,30.29) v3(-8.87,29.07) v3(-8.25,71.64) v3(-8.25,32.38) v3(-7.63,74.94) v3(-7.63,73.72) v3(-7.63,30.29) v3(-7.63,29.07) v3(-6.33,74.94) v3(-6.33,73.72) v3(-6.33,30.29) v3(-6.33,29.07) v3(-5.75,71.63) v3(-5.75,32.28)
P1V2_ADJ: length 5.7
  TOP w0.109: U36.4 122.35,23.95 122.32,23.93 121.61,23.93 R664.2 121.05,23.37 119.02,23.37 118.51,23.88 v3(118.38,23.88) R663.1
P1V2_RST_PG: length 14.8
  TOP w0.109: R4611.2 108.38,14.95 R4609.1 108.62,16.15 R4610.1 108.18,16.18 108.1,16.1 107.48,16.1 v3(106.92,16.66) 106.25,17.33 106.25,19.48 106.45,19.68 106.91,19.68 107.24,20.02 107.24,21.01 107.9,21.67 108.13,21.67 108.41,21.95 108.41,23.28 108.52,23.39 109.49,23.39 109.75,23.13 D25.2
P1V2_RST_PG_EN: length 7.3
  TOP w0.109: U45.2 107.42,19.48 107.65,19.71 109.75,19.71 109.75,19.7 D25.1 109.8,19.6 109.8,19.33 108.84,18.37 v3(108.84,17.9) 109.39,17.35 C310.2 R4610.2
P1V2_RST_PG_R: length 7.6
  TOP w0.109: R4611.1 107.85,14.15 108.31,13.7 108.31,12.8 107.44,11.94 107.44,10.99 108.33,10.1 108.99,10.1 v3(109.35,10.46) 109,10.81 U47.4
P1V2_STBY: length 11.9
  TOP w0.254: U35.H5 125.01,39.3 v4(125.02,39.3) ; v4(125.02,40.1) 125.01,40.1 U35.G5
  TOP w0.381: U35.F9 v4(128.22,40.9) ; U35.H13 v4(131.42,39.3) ; U35.N9 v4(128.22,34.5) ; U35.M6 v4(125.02,35.3) ; U35.F8 v4(126.62,40.9) ; U35.N8 v4(126.62,34.5) ; R4588.1 117.46,39.52 v3(117.22,39.75) ; U35.F10 v4(129.01,40.9) ; U35.K12 v4(130.62,36.9) ; U35.H12 v4(130.62,39.3) ; U35.J12 v4(130.62,37.7)
  BOTTOM w0.254: v4(125.02,35.3) 125.02,35.2 125.3,34.91 C211.1
  BOTTOM w0.305: v4(125.02,39.3) 124.91,39.3 124.6,39.6 C209.1 ; C220.1 124.62,40.4 124.92,40.1 v4(125.02,40.1)
  BOTTOM w0.381: v4(126.62,40.9) 126.23,40.51 C221.1 ; C223.1 128.61,34.89 v4(128.22,34.5) ; v4(129.01,40.9) C208.1 ; v4(128.22,40.9) C222.1
  vias: v3(117.22,40.39) v3(120.12,25.98) v3(120.12,25.27) v3(121.24,49.02) v3(121.24,48.39) v3(121.18,25.98) v3(121.18,25.27)
P1V2_STBY_BIC_SCALED: length 5.4
  TOP w0.178: 121.16,38.51 121.82,38.51 U35.H2
  TOP w0.254: R4588.2 C296.2 118.92,38.51 121.16,38.51
P1V2_STBY_EN_R: length 7.5
  TOP w0.109: v3(126.24,22.94) 126.42,22.94 126.56,23.08 126.56,23.35 126.45,23.45 U36.6
  BOTTOM w0.109: PR76.2 124.59,27.29 124.87,27 124.87,26.37 126.24,25 v3(126.24,22.94)
P1V2_VDD_PG_R: length 42.5
  TOP w0.109: U47.2 109.65,13.94 109.97,14.27 109.97,16.42 109.83,16.56 109.83,18.39 110.16,18.72 111.34,18.72 111.46,18.84 111.46,19.44 110.99,19.91 110.99,20.42 110.44,20.96 110.44,23.51 110.77,23.84 110.77,26.29 113.41,28.93 113.41,32.48 113.36,32.54 113.36,34.19 113.18,34.38 110.72,34.38 v3(110.69,34.35) ; U35.N3 v4(122.62,34.5)
  IN2 w0.124: v3(110.69,34.35) 110.73,34.39 112.88,34.39 115.16,32.11 116.74,32.11 117.27,32.64 v3(117.27,33.71)
  BOTTOM w0.109: v3(117.27,33.71) 117.47,33.5 118.85,33.5 119.27,33.08 R794.1 119.35,33.1 119.35,33.42 119.49,33.56 121.46,34.38 122.49,34.38 v4(122.62,34.5)
P3V3_AUX: length 267.8
  TOP w0.254: C85.1 90.45,46.53 U16.8 ; C75.1 43.66,46.99 42.61,48.04 U12.9 ; C78.1 69.32,30 68.54,30.77 U13.9 ; C81.1 97,37.84 95.95,38.9 U14.9 ; U35.G4 v4(123.42,40.1) ; R641.1 v4(127.51,48.38) ; R598.1 v3(137.16,30.48) ; R568.1 v3(125.35,28.7) ; R599.1 v3(137.16,31.5) ; U35.H4 v4(123.42,39.3) ; U45.5 106.77,21.37 107.02,21.62 ; R571.1 v3(130.43,28.7) ; v3(139.76,54.45) 139.91,54.6 C299.1 139.83,55.24 J2.1 ; U48.24 143.68,27.61 ; R565.1 v3(123.32,28.7) ; R600.1 v3(137.13,32.51) ; U11.9 16.47,49.8 17.53,48.74 C72.1 ; R602.1 v3(137.13,33.53)
  TOP w0.305: U35.L5 v4(124.22,36.1) ; R701.1 118.29,34.04 v3(117.93,34.39) ; R782.2 v3(123.19,48.39) ; R596.1 v3(132.59,48.39)
  TOP w0.356: U47.5 110.3,10.81 110.57,10.54 ; R533.2 R283.2 136.91,53.31 v3(136.65,53.57) ; R773.2 v3(135.64,48.39)
  TOP w0.381: R635.1 v3(125.22,49.02) ; R506.2 R282.2 136.75,41.66 v3(137.11,41.3) ; v3(70.36,25.65) 69.82,26.19 R202.2 ; R4609.2 109.42,14.57 v3(109.4,14.55) ; R4599.1 v3(116.9,10.82) ; U35.E8 v4(126.62,41.7) ; v3(68.61,29.92) 68.62,29.94 C78.1 ; U35.E9 v4(128.22,41.7) ; U35.N10 v4(129.01,34.5) ; R788.1 v3(128.52,48.36) ; U42.5 117.15,14.68 C306.1 117.1,15.02 v3(116.7,15.42) ; U35.G13 v4(131.42,40.1) ; v3(96.2,31.88) 96.2,32.3 R200.2 ; C84.2 119.56,56.9 119.99,57.32 120.7,57.32 121.05,57.68 U15.8 ; 111.61,11.04 111.11,10.54 110.57,10.54 ; 111.61,11.04 111.61,10.87 111.92,10.56 v3(111.92,10.33) ; 111.61,11.04 C311.1 ; v3(129.54,48.38) 129.54,48.38 R639.1 ; v3(43.23,52.32) 43.23,51.84 R233.2 ; v3(129.16,56.52) R4581.2 R4580.2 ; D24.A 117.97,55.36 117.7,55.09 117.7,53.32 117.99,53.03 v3(117.99,52.87) ; U35.G12 v4(130.62,40.1) ; v3(130.55,48.38) 130.56,48.37 R640.1 ; U35.E10 v4(129.01,41.7) ; 107.02,21.62 C308.1 v3(107.02,22.83) ; R4583.2 v3(129.16,58.55) ; R4649.1 59.05,22.71 v3(58.81,22.95) ; U35.K13 v4(131.42,36.9) ; R781.2 v3(126.36,51.05) ; U35.N7 v4(125.82,34.5) ; R572.1 v3(131.44,28.7) ; R783.2 v3(133.6,48.39) ; C92.1 116.06,14.68 R429.2 114.63,14.68 v3(114.45,14.5) ; v3(112.26,14.7) 112.38,14.58 R4598.1 ; R573.1 v3(133.48,28.7) ; U35.F13 v4(131.42,40.9) ; R413.1 v3(111.91,15.75) ; v3(144.25,28.55) 144.25,28.06 144.63,27.68 C314.1 144.57,27.61 143.68,27.61 ; R4639.1 12.08,37.52 v3(12.63,38.06) ; R528.2 v3(136.65,48.39) ; C91.1 111.86,17.73 112.17,18.03 R428.2 112.5,17.46 112.5,17.46 112.5,16.93 R412.2 v3(111.88,16.89) ; R646.1 v3(145.58,56.64) ; L6.1 v3(123.97,53.06) ; R90.1 v3(119.15,22.86) ; v3(62.99,34.92) 62.99,35.05 63.39,35.45 R248.2 ; R566.1 v3(126.36,28.7) ; R4582.2 v3(129.16,60.58) ; R636.1 v3(125.22,48.39) ; U35.L13 v4(131.42,36.1) ; v3(120.9,51.05) 120.9,51.42 R319.2 ; R789.2 v3(124.21,48.39) ; v3(120.14,13.08) 120.55,13.49 C307.1 120.99,13.02 U43.5 ; R697.1 v3(132.46,28.7) ; U35.L12 v4(130.62,36.1)
  TOP w0.457: R414.2 119.84,58.11 v3(119.64,57.9)
  TOP w0.508: 92.46,46.48 91.85,45.87 91.55,45.87 91.04,45.36 ; 92.46,46.48 93.36,46.48 93.87,45.97 R263.2 95.4,45.47 95.66,45.21 v3(96.01,45.21) ; 92.46,46.48 92.46,48.39 v3(91.82,49.02) ; v3(119.64,57.9) 119.51,57.78 119.51,57.66 119.15,57.3 C84.2 ; R217.2 v3(10.03,49.26) ; 91.04,45.36 91.03,45.36 90.42,45.97 90.42,46.5 C85.1 88.86,46.51 R288.1 ; 91.04,45.36 R264.2 ; v3(16.84,48.66) C72.1 ; v3(94.51,23.67) 94.51,24.35 R460.1 ; R262.2 90.42,36.45 v3(90.55,36.32) ; R179.2 73.84,51.58 v3(73.81,51.56) ; R232.2 35.31,46.35 v3(34.54,45.59) 34.54,47.99 35.08,48.52 35.08,48.54 v3(35.26,48.73) 36.93,48.73 R234.2 ; R247.2 v3(61.98,28.94) 61.9,28.86 R201.1 ; R249.2 61.98,31.9 v3(62.63,31.24) ; v3(9.91,54.23) 10.14,53.99 R218.2 ; R191.2 v3(17.42,44.75) ; v3(96.27,37.47) 96.43,37.47 96.69,37.73 96.96,37.73 C81.1 ; R190.1 10.8,45.49 10.46,45.49 10.44,45.47 v3(10.29,45.47) 9.78,45.97 v2(9.78,46.48) ; R182.2 99.66,52.3 v3(99.95,52.02) ; R199.1 v3(88.9,34.04) ; R219.2 v3(10.03,51.42) ; v3(42.98,46.91) C75.1
  IN1 w0.457: v3(43.23,52.32) 40.41,55.14 40.41,55.98 39.07,57.33 39.07,61.24 39.39,61.56 43.77,61.56 46.02,59.31 v3(46.02,58.9)
  IN1 w0.508: v3(42.98,46.91) 42.98,51.97 43.23,52.22 v3(43.23,52.32) ; v3(22.25,62.33) 22.25,61.15 21.74,60.64 14.73,60.64 14.22,60.13 14.22,55.73 12.26,53.76 11.01,53.76 10.54,54.23 v3(9.91,54.23)
  IN2 w0.457: v3(99.95,52.02) 97.57,49.64 92.71,49.64 92.09,49.02 v3(91.82,49.02)
  IN2 w0.508: v3(10.29,45.47) 10.87,45.47 12.4,43.94 v3(12.42,43.94)
  BOTTOM w0.254: v4(126.62,41.7) 126.62,41.58 ; 126.62,41.58 126.62,41.55 126.87,41.3 C213.1 ; 126.62,41.58 126.33,41.3 C210.1 ; v4(128.22,41.7) 128.22,41.6 127.91,41.3 C215.1 ; R598.1 v3(137.16,30.48) ; v4(131.42,36.9) C217.1 ; C234.1 130.35,40.49 130.62,40.22 v4(130.62,40.1) ; v4(130.62,36.1) 130.75,36.1 131.03,35.83 C212.1 131.28,35.45 131.28,35.12 131.08,34.91 C298.1 ; R611.1 137.08,28.45 v3(137.13,28.5) ; R613.1 v3(137.16,29.46) ; U44.10 142.5,26.62 142.76,26.87 142.9,26.87 143.61,27.58 C295.1 ; R714.1 v3(137.16,35.56) ; R4669.1 145.56,28.3 145.26,28.6 144.3,28.6 v3(144.25,28.55) ; R713.1 v3(137.16,34.54) ; R602.1 v3(137.13,33.53) ; R599.1 v3(137.16,31.5) ; R600.1 v3(137.13,32.51)
  BOTTOM w0.305: R708.1 118.24,28.7 v3(118.22,28.68) ; C297.1 131.82,37.31 v4(131.42,36.9) ; R185.1 v3(128.4,26.67) ; R596.1 v3(132.59,48.39)
  BOTTOM w0.33: C295.1 143.74,27.89 144.25,28.4 v3(144.25,28.55)
  BOTTOM w0.356: R4613.1 134.62,50.96 v3(135.26,51.6) ; R783.2 v3(133.6,48.39) ; R4618.1 131.57,50.94 v3(131.49,51.03) ; R639.1 129.54,48.37 v3(129.54,48.38) ; R788.1 v3(128.52,48.36)
  BOTTOM w0.381: v4(129.01,34.5) 129.4,34.89 C233.1 ; R627.1 v3(126.36,51.05) ; v3(117.99,52.87) 117.99,52.84 118.09,52.75 118.09,52.21 R751.1 ; v3(93.94,28.25) 93.7,28.01 92.87,28.01 R4654.1 ; R513.1 3.49,26.98 v3(3.49,28.41) ; v3(125.04,61.09) 125.04,61.34 125.44,61.74 R273.1 ; R776.2 144.32,36.96 145.21,36.07 v3(145.59,36.07) ; C90.1 C89.1 133.2,18.24 v3(133.81,18.24) ; R4668.1 v3(145.61,25.12) R4667.1 R4666.1 R4665.1 R4664.1 R4663.1 R4662.1 ; R4600.1 v3(139.8,22.53) ; R733.2 R707.1 119.25,26.68 v3(119.31,26.62) ; R458.1 65.69,21.49 65.39,21.18 64.19,21.18 63.6,21.77 63.6,23.69 v3(64.26,24.36) ; v4(131.42,36.1) 131.81,35.7 C218.1 ; v3(123.32,28.7) R565.1 R735.2 ; R4644.1 44.66,40.44 v3(44.17,40.44) ; C309.1 113.43,13.85 U46.5 ; C214.1 126.21,34.89 v4(125.82,34.5) ; R629.1 122.69,50.56 v3(123.19,51.05) 123.42,51.29 C235.1 ; v3(139.83,23.57) 139.7,23.44 R4660.1 R4659.1 ; R4604.2 R4605.2 v3(142.13,29.29) ; R426.2 R427.2 133.35,18.91 v3(133.81,18.91) 134.01,18.91 R4597.2 ; R571.1 v3(130.43,28.7) ; R635.1 v3(125.22,49.02) ; R456.1 41.98,42.07 42.01,42.07 42.08,42.14 R193.2 ; v3(139.8,21.62) R4601.1 R4661.1 ; R640.1 130.56,48.37 v3(130.55,48.38) ; R275.1 v3(125.08,57.93) ; R274.1 v3(124.99,58.91) ; C216.1 v4(124.22,36.1) ; R734.2 v3(126.36,28.7) ; R773.2 v3(135.64,48.39)
  BOTTOM w0.457: v3(112.26,14.7) 112.28,14.73 112.96,14.73 113.4,14.28 C309.1 ; R174.2 47.93,58.45 47.47,58.9 v3(46.02,58.9) ; R411.2 135.42,24.93 v3(135.41,24.92) R410.2
  BOTTOM w0.508: R171.2 22.63,62 22.3,62.33 v3(22.25,62.33) ; v3(38.84,36.98) 40.52,38.66 40.52,40.88 41.68,42.04 R456.1 ; v3(73.81,51.56) 73.81,50.27 73.38,49.83 73.38,42.92 74.35,41.96 v3(74.35,39.34) ; v3(91.82,49.02) 91.57,49.02 91.31,48.77 R287.1 R286.1 R295.2 ; v3(10.29,45.47) 10.47,45.65 R454.1
  vias: v3(9.73,41.94) v3(9.73,41.22) v3(10.36,41.94) v3(10.36,41.25) v3(38.1,36.83) v3(38.1,36.2) v3(38.86,36.32) v3(45.47,35.81) v3(46.1,35.81) v3(46.74,35.81) v3(64.24,25.12) v3(64.92,25.2) v3(64.92,24.51) v3(88.39,33.4) v3(88.39,32.77) v3(89.15,33.4) v3(89.15,32.77) v3(116.23,35.08) v3(116.87,35.08) v3(123.06,18.75) v3(123.06,18.11) v3(123.06,17.48) v3(126.9,20.37) v3(127.89,20.57) v3(128.62,55.12) v3(128.6,54.47) v3(128.65,20.52) v4(125.86,45.97) v4(125.86,45.34)
P3V3_AUX_BIC_SCALED: length 15.2
  TOP w0.254: U35.E3 v4(122.62,41.7)
  BOTTOM w0.254: R751.2 R753.1 C286.2 115.91,48.88 v1(115.91,48.5) 115.91,46.76 117.64,45.03 117.64,44.82 118.68,43.77 119.94,43.77 121.49,42.22 122.1,42.22 v4(122.62,41.7)
P3V3_DB800: length 34.4
  TOP w0.254: U32.25 41.12,31.21 v3(41.4,31.5) ; U32.15 40.62,24.91 40.91,24.62 v3(41.11,24.62) ; U32.11 38.62,24.78 38.46,24.62 v3(38.46,24.49)
  TOP w0.457: C149.1 37.56,23.58 v3(38.46,24.49)
  TOP w0.508: R476.1 36.88,33.49 v3(36.6,33.49) ; C150.1 v3(41.11,24.62) ; v3(41.4,31.5) 41.66,31.24 C148.1 C147.1 42.37,32.91 42.74,33.28 L4.2 42.1,35.18 39.98,35.18 R504.1
  IN2 w0.508: v3(36.6,33.49) 36.65,33.49 36.7,33.44 38.29,33.44 38.79,32.95 40.2,32.95 41.4,31.75 v3(41.4,31.5)
  BOTTOM w0.508: 40.13,30.37 39.12,30.37 38.86,30.12 37.97,30.12 R478.1 ; v3(38.46,24.49) 38.59,24.62 v1(39.62,24.62) v3(41.11,24.62) 41.11,25.03 42.05,25.97 42.05,31.09 41.4,31.73 v3(41.4,31.5)
P3V3_DB800A: length 30.3
  TOP w0.254: U32.4 36.44,28.19 36.27,28.02 C159.1 ; v3(42.84,28.19) U32.21
  TOP w0.406: C158.1 43.36,27.39 42.84,27.91 v3(42.84,28.19)
  TOP w0.508: v3(34.77,27.32) 34.77,27.49 35.3,28.02 C159.1 ; R504.2 38.07,35.31 37.56,34.8 v2(37.56,33.97) 38.68,32.85 C157.1 38.68,31.6 v3(38.32,31.24)
  IN2 w0.457: v3(42.72,25.2) 42.26,25.2 42.02,25.43 39.69,25.43 39.24,25.88 37.58,25.88 36.15,27.32 v3(34.77,27.32) 37.08,29.63 37.08,30.59 36.59,31.09 36.59,31.5 37.04,31.95 37.61,31.95 v3(38.32,31.24)
  BOTTOM w0.457: v3(42.84,28.19) 42.85,28.19 v1(43.69,27.35) 43.69,26.16 v3(42.72,25.2)
P3V3_E1S_0: length 123.1
  TOP w0.508: R215.2 35.94,37.7 35.94,36.7 v3(35.59,36.35) ; v3(36.6,39.29) 36.47,39.17 R216.2
  IN1 w0.508: v3(35.59,36.35) 35.31,36.07 32.21,36.07 31.39,36.88 29.41,36.88 28.33,37.96 25.11,37.96 v3(24.59,38.48)
  VCC w0.508: v3(118.49,48.72) 118.03,48.72 117.17,47.85 117.17,47.09 116.12,46.04 114.96,46.04 114.45,45.53 114.45,44.15 115.14,43.46 115.14,41.63 113.67,40.16 111.66,40.16 110.64,41.17 105.37,41.17 104.77,41.77 96.43,41.77 95.55,40.89 95.55,38.99 94.98,38.42 91.91,38.42 90.96,37.47 90.04,37.47 88.9,36.32 82.01,36.32 81.81,36.53 81.26,36.53 80.87,36.14 80.87,36.12 80.39,35.64 80.39,33.34 79.18,32.13 79.18,31.5 78.68,30.99 77.34,30.99 74.93,28.57 74.86,28.57 74.48,28.19 68.41,28.19 65.87,29.25 64.02,30.48 62.41,30.48 61.06,31.83 61.06,34.37 60.35,35.08 58.56,35.08 57.49,36.16 57.44,36.16 55.02,38.58 51.36,38.58 50.52,39.42 48.87,39.42 48.26,38.81 38.84,38.81 38.76,38.89 37.01,38.89 v3(36.6,39.29) 35.81,38.51 35.81,36.58 v3(35.59,36.35)
  BOTTOM w0.381: R767.1 118,49.02 118.26,48.77 118.44,48.77 v3(118.49,48.72)
  vias: v2(22.2,38.6)
P3V3_E1S_0_CB: length 8.4
  TOP w0.109: U26.B1 13.57,38.61 12.69,38.61 11.31,38.04 8.1,38.04 7.65,38.49 v2(7.65,38.79) 8.28,38.79 8.46,38.61 R455.1
P3V3_E1S_0_DVDT: length 3.4
  TOP w0.109: U7.1 13.27,46.17 13.08,46.36 12.19,46.36 11.83,46.71 C60.1 11.18,47.39 v2(11.18,48.01)
P3V3_E1S_0_GATE: length 1.7
  TOP w0.109: U26.A6 13.2,41.54 v3(13.03,41.7)
  BOTTOM w0.109: v3(13.03,41.7) 12.52,41.7 12.44,41.63 C115.1
P3V3_E1S_0_ILM: length 4.4
  TOP w0.109: v2(18.92,45.09) 18.92,45.34 18.3,45.97 17.12,45.97 R189.1 16.42,45.67 U7.7
P3V3_E1S_0_ISENSE: length 2.2
  TOP w0.109: U26.A1 12.24,39.04 v3(12.04,38.83) 11.67,38.83 R490.1
P3V3_E1S_0_OV: length 3
  TOP w0.203: R492.1 R491.2 16.36,39.64 v3(16.21,39.8) 15.97,40.04 U26.D3
P3V3_E1S_0_REG: length 2.3
  TOP w0.109: C128.2 15.54,37.54 v3(15.54,38.1) 15.54,38.5 U26.D1
P3V3_E1S_0_SCALED: length 10.3
  TOP w0.254: U35.D3 v4(122.62,42.5)
  BOTTOM w0.254: v4(122.62,42.5) 122.32,42.8 121.65,42.8 118.61,45.83 v1(117.75,45.83) 117.1,46.49 117.1,47.04 C293.2 R770.1 R767.2
P3V3_E1S_1: length 95.6
  TOP w0.508: R231.2 R230.2 62.31,38.15 62.75,37.71 62.75,36.87 62.05,36.17 60.98,36.17 v3(60.57,36.58)
  IN1 w0.508: v3(60.57,36.58) 60.19,36.2 59.31,36.2 57.59,37.91 55.12,37.91 54.46,38.58 51.53,38.58 v3(50.85,37.9)
  VCC w0.508: v3(120.55,49.38) 119.68,50.24 119.68,50.24 119.2,50.72 119.2,50.72 119.18,50.75 119.18,51.03 118.67,51.54 117.45,51.54 116.94,51.03 116.94,50.42 116.33,49.81 116.33,47.6 115.54,46.81 114.32,46.81 112.79,45.28 111.83,45.28 109.32,42.77 106.35,42.77 106.11,42.53 94.8,42.53 90.63,38.35 89.84,38.35 88.57,37.08 82.88,37.08 82.68,37.29 80.95,37.29 80.11,36.45 80.11,36.44 79.63,35.95 79.63,33.65 78.74,32.77 77.98,32.77 74.17,28.96 68.62,28.96 66.29,29.92 63.85,31.55 61.82,33.58 61.82,36.07 61.32,36.58 v3(60.57,36.58)
  BOTTOM w0.381: R771.1 119.91,49.04 120.14,49.28 120.45,49.28 v3(120.55,49.38)
  vias: v2(50.04,37.21)
P3V3_E1S_1_CB: length 1.6
  TOP w0.109: U27.B1 43.08,36.33 42.96,36.21 v3(42.96,36.13)
  BOTTOM w0.109: v3(42.96,36.13) 43.13,35.97 R457.1
P3V3_E1S_1_DVDT: length 2.8
  TOP w0.109: v3(41.69,44.65) 41.54,44.65 41.43,44.54 41.43,44.2 41.52,44.11 U8.1
  BOTTOM w0.109: C61.1 42.09,44.25 v3(41.69,44.65)
P3V3_E1S_1_GATE: length 3.2
  TOP w0.109: v3(42.06,39.67) 42.06,39.56 42.17,39.46 U27.A6
  BOTTOM w0.109: v3(42.06,39.67) 41.57,39.18 v1(41.46,39.18) 41.35,39.29 41.35,40.13 41.53,40.32 C118.1
P3V3_E1S_1_ILM: length 3
  TOP w0.109: R192.1 45.52,44.3 v2(45.44,44.39) 45.24,44.39 44.46,43.61 U8.7
P3V3_E1S_1_ISENSE: length 2.2
  TOP w0.109: U27.A1 42.53,36.96 42.19,36.61 v3(42.15,36.61)
  BOTTOM w0.109: R496.1 42.16,35.3 42.49,35.64 42.49,36.27 v3(42.15,36.61)
P3V3_E1S_1_OV: length 6.9
  TOP w0.203: v3(45.69,36.45) 45.69,36.63 44.37,37.96 U27.D3
  BOTTOM w0.109: R497.1 44.39,37.95 44.71,38.27 v1(45.33,38.27) 45.88,38.27 46.15,38.01 R495.2 45.69,36.66 v3(45.69,36.45)
P3V3_E1S_1_REG: length 1.6
  TOP w0.109: U27.D1 44.32,36.71 v3(44.32,36.32)
  BOTTOM w0.109: v3(44.32,36.32) 44.32,35.71 C129.2
P3V3_E1S_1_SCALED: length 7.4
  TOP w0.109: U35.C2 v4(121.82,43.3)
  BOTTOM w0.254: v4(121.82,43.3) 121.82,43.46 119.6,45.68 v1(119.6,45.84) 119.6,46.24 119.11,46.73 C294.2 R772.1 R771.2
